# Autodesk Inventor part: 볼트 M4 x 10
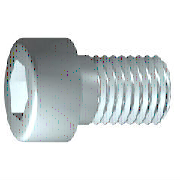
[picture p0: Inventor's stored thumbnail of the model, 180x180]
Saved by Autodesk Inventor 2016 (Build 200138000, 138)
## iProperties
IsCustomPart: 0
Created: 2012-02
Part Number: 볼트 M4 x 10
Material: 스테인리스강
Description: 6각 소켓 머리 캡 나사
Document SubType Name: Modeling
Standard: ISO 4762
Designer: mduedu
Standard Revision: Fourth edition 2004-03-01
Standards Organization: ISO
Language: ko-KR
Size Designation: M4 x 10
Categories: <MemberInstance><Categories><Category DisplayName="조임쇠" InternalName="e4da775c-781d-43d5-af7c-5136215cf5a6" Mnemonic="FSTN"><Category DisplayName="볼트" InternalN
Density: 8.08 g/cm^3
Appearance: 반광택
Mass: 2.09412 g
Surface Area: 3.0572 cm^2
Volume: 0.259174 cm^3
Author: mduedu
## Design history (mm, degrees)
sketch "스케치1"
  geometry: L1 (-1, 0)-(10, 0); L2 (10, 0)-(10, 2); L3 (10, 2)-(1.75, 2); L4 (1.75, 2)-(1.32, 2); L5 (1.32, 2)-(0, 2); L6 (0, 2)-(0, 3.5); L7 (0, 3.5)-(-4, 3.5); L8 (-4, 3.5)-(-4, 1.732); L9 (-4, 1.732)-(-2, 1.732); L10 (-2, 1.732)-(-1, 0); L11 (-6.8, 0)-(12.8, 0) reference; L12 (0, -0.7)-(0, 4.2) reference; L13 (1.75, 2)-(0, 2)
  constraints: 22 end point, 6 parallel, 2 collinear, 2 perpendicular, 1 horizontal, 1 point on line
  dimensions: "d1" = 8.25 distance from line of L3.end L2 (= GEL); "d2" = 0.42952 distance of L4.end L3.end (computed from GAL); "d3" = 4 distance between parallel lines of L8 L6 (= KOH); "d4" = 2 distance of L8.end L9.end (= INTI); "d5" = 60 deg angle of L10 L1; "d6" = 4 diameter of L3 L1 (= GD); "d7" = 4 diameter of L5 L1 (= BDM); "d8" = 3.4641 diameter of L9 L1 (= 1.1547 x SW); "d9" = 7 diameter of L7 L1 (= KOD); "d26" = 10 distance between parallel lines of L12 L2 (= NLG)
revolve "본체" sketch "스케치1" stored, may be unused: angle "d10" = 90 deg
sketch "스케치2"
  geometry: L1 (0, -4.9)-(0, 4.9) reference; L2 (-4.9, 0)-(4.9, 0) reference; L3 (1.732, 0)-(0.866, -1.5); L4 (0.866, -1.5)-(-0.866, -1.5); L5 (-0.866, -1.5)-(-1.732, 0); L6 (-1.732, 0)-(-0.866, 1.5); L7 (-0.866, 1.5)-(0.866, 1.5); L8 (0.866, 1.5)-(1.732, 0); 2 further points
  constraints: 12 end point, 1 coincident, 1 horizontal alignment, 1 point on line, 12 other
extrude "슬롯" join sketch "스케치2" stored distance "d11" = 10; taper "d12" = 0 deg
workplane "Work Plane1"
fillet "Fillet2" dims "d30" = 0.1 (= R)
body "Solid1"
fillet "모깎기1" dims "d17" = 0.4 (= RR)
feature "스레드" dims "d13" = 8.25 (= GEL), "d14" = 0
chamfer "모따기1" distance "d15" = 0.42941 (= -0.5 x SPD + 0.5 x GD); stored, may be unused: second distance "d16" = 0.42941 (= GUL), angle "d27" = 45 deg
other parameters: "GD" = 4 [user parameter; used in 2 equation terms], "NLG" = 10 [user parameter; used in 1 equation term], "GEL" = 8.25 [user parameter; used in 2 equation terms], "KOD" = 7 [user parameter; used in 1 equation term], "KOH" = 4 [user parameter; used in 1 equation term], "INTI" = 2 [user parameter; used in 1 equation term], "GAL" = 0.42941 (= 0.61345 x PTC) [user parameter; used in 1 equation term], "GUL" = 0.42941 (= 0.61345 x PTC) [user parameter; used in 1 equation term], "BDM" = 4 (= NND) [user parameter; used in 1 equation term], "SW" = 3 [user parameter; used in 2 equation terms], "RR" = 0.4 [user parameter; used in 1 equation term], "SPD" = 3.14117 (= NND - 1.2269 x PTC) [user parameter; used in 1 equation term], "d19" = 0, "d28" = 0, "d29" = 0, "R" = 0.1 [user parameter; used in 1 equation term], "TOA" = 30 deg [user parameter], "GD1" = 3.14117 (= THREADDIA - 1.2269 x PTC) [user parameter], "THREADDIA" = 4 [user parameter; used in 1 equation term], "FAWI" = 45 deg [user parameter], "TPU" = 14.28571 (computed from PTC) [user parameter], "PTC" = 0.7 [user parameter; used in 5 equation terms], "NND" = 4 [user parameter; used in 2 equation terms], "E0" = 3.465 (= 1.155 x SW) [user parameter]
